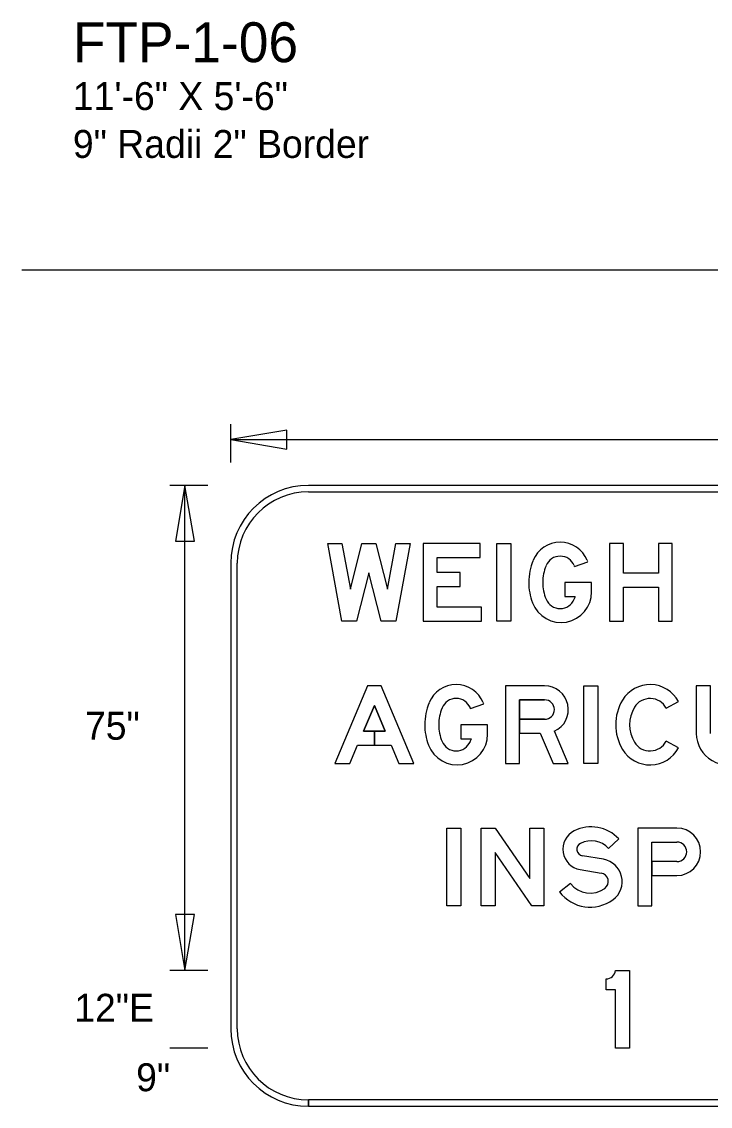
# Model space of a CAD drawing. Extents: x 0 to 770, y 0 to 495.
# Drawn here: x 0 to 86.3, y 225.2 to 361.1 of the extents above; entities that cross this region are included whole.
import ezdxf

# ---------------------------------------------------------------- set-up
doc = ezdxf.new("R2010")
doc.units = 0
for name, color, linetype in [('Dimension', 7, 'Continuous'), ('GSBWFill', 7, 'Continuous'), ('GSColorFill', 7, 'Continuous'), ('GSDims', 7, 'Continuous'), ('GSOutline', 7, 'Continuous'), ('SheetLines_dp', 7, 'Continuous'), ('TextStructures', 7, 'Continuous')]:
    doc.layers.add(name, color=color, linetype=linetype)

msp = doc.modelspace()

# ---------------------------------------------------------------- linework, layer by layer
at = {"layer": 'Dimension'}
for points in [[(26.22, 308.76), (33.24, 307.57), (33.24, 309.95)], [(20.47, 303.01), (19.28, 296), (21.66, 296)], [(20.47, 303.01), (19.28, 296), (21.66, 296)], [(20.47, 242.21), (21.66, 249.22), (19.28, 249.22)]]:
    msp.add_lwpolyline(points, close=True, dxfattribs=at)
at = {"layer": 'GSBWFill'}
for p, q in [((152.7, 303.01), (35.95, 303.01)), ((152.7, 303.01), (35.95, 303.01)), ((35.95, 302.2), (152.7, 302.2)), ((26.22, 293.28), (26.22, 234.91)), ((26.22, 293.28), (26.22, 234.91)), ((27.03, 234.91), (27.03, 293.28)), ((69.33, 292.86), (70.98, 293.45)), ((71.46, 289.65), (71.46, 290.85)), ((56.29, 275.03), (57.94, 275.62)), ((80.81, 275.09), (82.36, 275.91)), ((58.42, 271.81), (58.42, 273.01)), ((82.36, 270.12), (80.81, 270.94)), ((80.81, 270.94), (80.81, 270.94)), ((73.58, 257.51), (74.86, 258.7)), ((79, 258.29), (82.16, 258.29)), ((72.95, 256.14), (70.3, 256.59)), ((70.01, 254.86), (72.66, 254.41)), ((68.81, 253.11), (67.42, 252.04)), ((35.95, 225.18), (35.95, 225.99)), ((152.7, 225.99), (35.96, 225.99)), ((35.96, 225.99), (35.96, 225.18)), ((35.95, 225.18), (152.7, 225.18)), ((35.96, 225.18), (152.7, 225.18))]:
    msp.add_line(p, q, dxfattribs=at)
for points in [[(43.54, 292.07), (42, 285.99), (40.16, 285.99), (38.38, 295.72), (40.16, 295.72), (41.21, 289.99), (42.65, 295.72), (44.42, 295.72), (45.87, 289.99), (46.91, 295.72), (48.69, 295.72), (46.92, 285.99), (45.07, 285.99)], [(57.64, 287.74), (52.1, 287.74), (52.1, 290.35), (54.97, 290.35), (54.97, 292.11), (52.1, 292.11), (52.1, 293.96), (57.5, 293.96), (57.5, 295.72), (50.35, 295.72), (50.35, 285.99), (57.64, 285.99)], [(59.59, 285.99), (59.59, 295.72), (61.34, 295.72), (61.34, 285.99)], [(79.83, 292.02), (75.45, 292.02), (75.45, 295.72), (73.7, 295.72), (73.7, 285.99), (75.45, 285.99), (75.45, 290.27), (79.83, 290.27), (79.83, 285.99), (81.58, 285.99), (81.58, 295.72), (79.83, 295.72)], [(45.58, 272.19), (44.22, 272.19), (44.22, 270.44), (46.32, 270.44), (47.28, 268.15), (49.18, 268.15), (45.09, 277.88), (43.34, 277.88), (39.26, 268.15), (41.16, 268.15), (42.12, 270.44), (44.22, 270.44), (44.22, 272.19), (42.85, 272.19), (44.22, 275.44)], [(70.49, 268.15), (70.49, 277.88), (72.24, 277.88), (72.24, 268.15)], [(53.31, 250.31), (53.31, 260.04), (55.07, 260.04), (55.07, 250.31)], [(65.48, 260.04), (65.48, 250.31), (63.97, 250.31), (59.35, 256.98), (59.35, 250.31), (57.6, 250.31), (57.6, 260.04), (59.35, 260.04), (63.72, 253.74), (63.72, 260.04)]]:
    msp.add_lwpolyline(points, close=True, dxfattribs=at)
for points in [[(71.46, 290.85), (68.1, 290.85), (68.1, 289.1), (69.42, 289.1)], [(65.57, 277.88), (60.66, 277.88), (60.66, 268.15), (62.41, 268.15), (62.41, 276.13), (65.57, 276.13)], [(86.35, 271.92), (86.35, 277.88), (84.59, 277.88), (84.59, 271.92)], [(65.57, 273.7), (62.41, 273.7), (62.41, 271.94)], [(58.42, 273.01), (55.07, 273.01), (55.07, 271.26), (56.38, 271.26)], [(62.41, 271.94), (64.99, 271.94), (66.63, 268.15), (68.54, 268.15), (66.79, 272.2)], [(82.16, 260.04), (77.25, 260.04), (77.25, 250.31), (79, 250.31), (79, 258.29)], [(82.16, 255.86), (79, 255.86), (79, 254.11), (82.16, 254.11)], [(74.45, 242.21), (76.2, 242.21), (76.2, 232.48)], [(76.2, 232.48), (74.45, 232.48), (74.45, 239.77), (73.28, 239.77), (73.28, 241.14)]]:
    msp.add_lwpolyline(points, dxfattribs=at)
for centre, radius, start, end in [((35.95, 293.28), 9.73, 90, 180), ((35.95, 293.28), 9.73, 90, 180), ((35.95, 293.28), 8.92, 90, 180), ((67.52, 292.22), 3.67, 22.4256, 157.5744), ((67.52, 292.22), 1.92, 22.4256, 157.5744), ((70.83, 290.85), 7.25, 157.5744, 180), ((70.83, 290.85), 5.5, 157.5744, 180), ((64.21, 290.85), 5.5, 21.4721, 22.4256), ((64.21, 290.85), 7.25, 21.0425, 22.4256), ((70.83, 290.85), 7.25, 180, 200.6303), ((67.63, 289.65), 3.83, 200.6303, 0), ((70.83, 290.85), 5.5, 180, 202.4256), ((67.52, 289.49), 1.92, 202.4256, 337.5744), ((64.21, 290.85), 5.5, 337.5744, 341.4227), ((70.44, 257.4), 2.58, 116.9123, 260.4087), ((71.41, 255.49), 4.72, 42.8759, 116.9123), ((71.41, 255.49), 2.97, 42.8759, 116.9123), ((70.44, 257.4), 0.827, 116.9123, 260.4087), ((72.48, 253.36), 2.82, 306.123, 80.4087), ((72.48, 253.36), 1.07, 306.123, 80.4087), ((71.28, 255.01), 3.11, 217.5895, 306.123), ((71.28, 255.01), 4.86, 217.5895, 306.123), ((73.28, 242.31), 1.17, 270, 355.0209), ((35.95, 234.91), 9.73, 180, 270), ((35.95, 234.91), 9.73, 180, 270), ((35.95, 234.91), 8.92, 180, 270)]:
    msp.add_arc(centre, radius, start, end, dxfattribs=at)
for centre, major_axis, start_param, end_param in [((54.48, 274.38), (0, 3.67), 5.10379, 7.46258), ((65.57, 274.91), (0, 2.97), 3.562504, 6.283185), ((78.79, 274.01), (0, 4.04), 5.201543, 7.308565), ((54.48, 274.38), (0, 1.92), 5.10379, 7.46258), ((65.57, 274.91), (0, 1.22), 3.141593, 6.283185), ((80.44, 273.01), (0, 5.96), 1.025379, 2.116213), ((78.79, 274.01), (0, 2.29), 5.201543, 7.308565), ((57.79, 273.01), (0, 7.25), 1.179395, 1.570796), ((57.79, 273.01), (0, 5.5), 1.179395, 1.570796), ((51.17, 273.01), (0, 5.5), 5.087148, 5.10379), ((51.17, 273.01), (0, 7.25), 5.07965, 5.10379), ((80.44, 273.01), (0, 4.21), 1.025379, 2.116213), ((57.79, 273.01), (0, 7.25), 1.570796, 1.930863), ((57.79, 273.01), (0, 5.5), 1.570796, 1.962198), ((88.53, 271.92), (0, 3.94), 1.570796, 4.712389), ((54.59, 271.81), (0, 3.83), 1.930863, 4.712389), ((54.48, 271.65), (0, 1.92), 1.962198, 4.320988), ((51.17, 273.01), (0, 5.5), 4.320988, 4.388154), ((78.79, 272.02), (0, 2.29), 2.116213, 4.223235), ((78.79, 272.02), (0, 4.04), 2.116213, 4.223235), ((82.16, 257.08), (0, 2.97), 3.141593, 6.283185), ((82.16, 257.08), (0, 1.22), 3.141593, 6.283185)]:
    msp.add_ellipse(centre, major_axis=major_axis, ratio=0.999994, start_param=start_param, end_param=end_param, dxfattribs=at)
at = {"layer": 'GSColorFill'}
for p, q in [((69.33, 292.86), (70.98, 293.45)), ((71.46, 289.65), (71.46, 290.85)), ((56.29, 275.03), (57.94, 275.62)), ((80.81, 275.09), (82.36, 275.91)), ((58.42, 271.81), (58.42, 273.01)), ((82.36, 270.12), (80.81, 270.94)), ((80.81, 270.94), (80.81, 270.94)), ((73.58, 257.51), (74.86, 258.7)), ((79, 258.29), (82.16, 258.29)), ((72.95, 256.14), (70.3, 256.59)), ((70.01, 254.86), (72.66, 254.41)), ((68.81, 253.11), (67.42, 252.04))]:
    msp.add_line(p, q, dxfattribs=at)
for points in [[(43.54, 292.07), (42, 285.99), (40.16, 285.99), (38.38, 295.72), (40.16, 295.72), (41.21, 289.99), (42.65, 295.72), (44.42, 295.72), (45.87, 289.99), (46.91, 295.72), (48.69, 295.72), (46.92, 285.99), (45.07, 285.99)], [(57.64, 287.74), (52.1, 287.74), (52.1, 290.35), (54.97, 290.35), (54.97, 292.11), (52.1, 292.11), (52.1, 293.96), (57.5, 293.96), (57.5, 295.72), (50.35, 295.72), (50.35, 285.99), (57.64, 285.99)], [(59.59, 285.99), (59.59, 295.72), (61.34, 295.72), (61.34, 285.99)], [(79.83, 292.02), (75.45, 292.02), (75.45, 295.72), (73.7, 295.72), (73.7, 285.99), (75.45, 285.99), (75.45, 290.27), (79.83, 290.27), (79.83, 285.99), (81.58, 285.99), (81.58, 295.72), (79.83, 295.72)], [(45.58, 272.19), (44.22, 272.19), (44.22, 270.44), (46.32, 270.44), (47.28, 268.15), (49.18, 268.15), (45.09, 277.88), (43.34, 277.88), (39.26, 268.15), (41.16, 268.15), (42.12, 270.44), (44.22, 270.44), (44.22, 272.19), (42.85, 272.19), (44.22, 275.44)], [(70.49, 268.15), (70.49, 277.88), (72.24, 277.88), (72.24, 268.15)], [(53.31, 250.31), (53.31, 260.04), (55.07, 260.04), (55.07, 250.31)], [(65.48, 260.04), (65.48, 250.31), (63.97, 250.31), (59.35, 256.98), (59.35, 250.31), (57.6, 250.31), (57.6, 260.04), (59.35, 260.04), (63.72, 253.74), (63.72, 260.04)]]:
    msp.add_lwpolyline(points, close=True, dxfattribs=at)
for points in [[(71.46, 290.85), (68.1, 290.85), (68.1, 289.1), (69.42, 289.1)], [(65.57, 277.88), (60.66, 277.88), (60.66, 268.15), (62.41, 268.15), (62.41, 276.13), (65.57, 276.13)], [(86.35, 271.92), (86.35, 277.88), (84.59, 277.88), (84.59, 271.92)], [(65.57, 273.7), (62.41, 273.7), (62.41, 271.94)], [(58.42, 273.01), (55.07, 273.01), (55.07, 271.26), (56.38, 271.26)], [(62.41, 271.94), (64.99, 271.94), (66.63, 268.15), (68.54, 268.15), (66.79, 272.2)], [(82.16, 260.04), (77.25, 260.04), (77.25, 250.31), (79, 250.31), (79, 258.29)], [(82.16, 255.86), (79, 255.86), (79, 254.11), (82.16, 254.11)], [(74.45, 242.21), (76.2, 242.21), (76.2, 232.48)], [(76.2, 232.48), (74.45, 232.48), (74.45, 239.77), (73.28, 239.77), (73.28, 241.14)]]:
    msp.add_lwpolyline(points, dxfattribs=at)
for centre, radius, start, end in [((67.52, 292.22), 3.67, 22.4256, 157.5744), ((67.52, 292.22), 1.92, 22.4256, 157.5744), ((70.83, 290.85), 7.25, 157.5744, 180), ((70.83, 290.85), 5.5, 157.5744, 180), ((64.21, 290.85), 5.5, 21.4721, 22.4256), ((64.21, 290.85), 7.25, 21.0425, 22.4256), ((70.83, 290.85), 7.25, 180, 200.6303), ((67.63, 289.65), 3.83, 200.6303, 0), ((70.83, 290.85), 5.5, 180, 202.4256), ((67.52, 289.49), 1.92, 202.4256, 337.5744), ((64.21, 290.85), 5.5, 337.5744, 341.4227), ((70.44, 257.4), 2.58, 116.9123, 260.4087), ((71.41, 255.49), 4.72, 42.8759, 116.9123), ((71.41, 255.49), 2.97, 42.8759, 116.9123), ((70.44, 257.4), 0.827, 116.9123, 260.4087), ((72.48, 253.36), 2.82, 306.123, 80.4087), ((72.48, 253.36), 1.07, 306.123, 80.4087), ((71.28, 255.01), 3.11, 217.5895, 306.123), ((71.28, 255.01), 4.86, 217.5895, 306.123), ((73.28, 242.31), 1.17, 270, 355.0209)]:
    msp.add_arc(centre, radius, start, end, dxfattribs=at)
for centre, major_axis, start_param, end_param in [((54.48, 274.38), (0, 3.67), 5.10379, 7.46258), ((65.57, 274.91), (0, 2.97), 3.562504, 6.283185), ((78.79, 274.01), (0, 4.04), 5.201543, 7.308565), ((54.48, 274.38), (0, 1.92), 5.10379, 7.46258), ((65.57, 274.91), (0, 1.22), 3.141593, 6.283185), ((80.44, 273.01), (0, 5.96), 1.025379, 2.116213), ((78.79, 274.01), (0, 2.29), 5.201543, 7.308565), ((57.79, 273.01), (0, 7.25), 1.179395, 1.570796), ((57.79, 273.01), (0, 5.5), 1.179395, 1.570796), ((51.17, 273.01), (0, 5.5), 5.087148, 5.10379), ((51.17, 273.01), (0, 7.25), 5.07965, 5.10379), ((80.44, 273.01), (0, 4.21), 1.025379, 2.116213), ((57.79, 273.01), (0, 7.25), 1.570796, 1.930863), ((57.79, 273.01), (0, 5.5), 1.570796, 1.962198), ((88.53, 271.92), (0, 3.94), 1.570796, 4.712389), ((54.59, 271.81), (0, 3.83), 1.930863, 4.712389), ((54.48, 271.65), (0, 1.92), 1.962198, 4.320988), ((51.17, 273.01), (0, 5.5), 4.320988, 4.388154), ((78.79, 272.02), (0, 2.29), 2.116213, 4.223235), ((78.79, 272.02), (0, 4.04), 2.116213, 4.223235), ((82.16, 257.08), (0, 2.97), 3.141593, 6.283185), ((82.16, 257.08), (0, 1.22), 3.141593, 6.283185)]:
    msp.add_ellipse(centre, major_axis=major_axis, ratio=0.999994, start_param=start_param, end_param=end_param, dxfattribs=at)
at = {"layer": 'GSDims'}
for p, q in [((26.22, 305.89), (26.22, 310.67)), ((26.22, 308.76), (162.43, 308.76)), ((23.35, 303.01), (18.56, 303.01)), ((20.47, 242.21), (20.47, 303.01)), ((23.35, 242.21), (18.56, 242.21)), ((23.35, 242.21), (18.56, 242.21)), ((23.35, 232.48), (18.56, 232.48)), ((23.35, 232.48), (18.56, 232.48))]:
    msp.add_line(p, q, dxfattribs=at)
at = {"layer": 'GSOutline'}
for p, q in [((69.33, 292.86), (70.98, 293.45)), ((71.46, 289.65), (71.46, 290.85)), ((56.29, 275.03), (57.94, 275.62)), ((80.81, 275.09), (82.36, 275.91)), ((62.41, 273.7), (65.57, 273.7)), ((58.42, 271.81), (58.42, 273.01)), ((82.36, 270.12), (80.81, 270.94)), ((80.81, 270.94), (80.81, 270.94)), ((73.58, 257.51), (74.86, 258.7)), ((79, 258.29), (82.16, 258.29)), ((72.95, 256.14), (70.3, 256.59)), ((70.01, 254.86), (72.66, 254.41)), ((68.81, 253.11), (67.42, 252.04)), ((79, 254.11), (82.16, 254.11))]:
    msp.add_line(p, q, dxfattribs=at)
for points in [[(43.54, 292.07), (42, 285.99), (40.16, 285.99), (38.38, 295.72), (40.16, 295.72), (41.21, 289.99), (42.65, 295.72), (44.42, 295.72), (45.87, 289.99), (46.91, 295.72), (48.69, 295.72), (46.92, 285.99), (45.07, 285.99)], [(57.64, 287.74), (52.1, 287.74), (52.1, 290.35), (54.97, 290.35), (54.97, 292.11), (52.1, 292.11), (52.1, 293.96), (57.5, 293.96), (57.5, 295.72), (50.35, 295.72), (50.35, 285.99), (57.64, 285.99)], [(59.59, 285.99), (59.59, 295.72), (61.34, 295.72), (61.34, 285.99)], [(79.83, 292.02), (75.45, 292.02), (75.45, 295.72), (73.7, 295.72), (73.7, 285.99), (75.45, 285.99), (75.45, 290.27), (79.83, 290.27), (79.83, 285.99), (81.58, 285.99), (81.58, 295.72), (79.83, 295.72)], [(42.12, 270.44), (46.32, 270.44), (47.28, 268.15), (49.18, 268.15), (45.09, 277.88), (43.34, 277.88), (39.26, 268.15), (41.16, 268.15)], [(70.49, 268.15), (70.49, 277.88), (72.24, 277.88), (72.24, 268.15)], [(45.58, 272.19), (44.22, 275.44), (42.85, 272.19)], [(53.31, 250.31), (53.31, 260.04), (55.07, 260.04), (55.07, 250.31)], [(65.48, 260.04), (65.48, 250.31), (63.97, 250.31), (59.35, 256.98), (59.35, 250.31), (57.6, 250.31), (57.6, 260.04), (59.35, 260.04), (63.72, 253.74), (63.72, 260.04)]]:
    msp.add_lwpolyline(points, close=True, dxfattribs=at)
for points in [[(71.46, 290.85), (68.1, 290.85), (68.1, 289.1), (69.42, 289.1)], [(65.57, 277.88), (60.66, 277.88), (60.66, 268.15), (62.41, 268.15), (62.41, 271.94), (64.99, 271.94)], [(86.35, 271.92), (86.35, 277.88), (84.59, 277.88), (84.59, 271.92)], [(65.57, 276.13), (62.41, 276.13), (62.41, 273.7)], [(58.42, 273.01), (55.07, 273.01), (55.07, 271.26), (56.38, 271.26)], [(64.99, 271.94), (66.63, 268.15), (68.54, 268.15), (66.79, 272.2)], [(82.16, 260.04), (77.25, 260.04), (77.25, 250.31), (79, 250.31), (79, 254.11)], [(82.16, 255.86), (79, 255.86), (79, 258.29)], [(74.45, 242.21), (76.2, 242.21), (76.2, 232.48)], [(76.2, 232.48), (74.45, 232.48), (74.45, 239.77), (73.28, 239.77), (73.28, 241.14)]]:
    msp.add_lwpolyline(points, dxfattribs=at)
for centre, radius, start, end in [((67.52, 292.22), 3.67, 22.4256, 157.5744), ((67.52, 292.22), 1.92, 22.4256, 157.5744), ((70.83, 290.85), 7.25, 157.5744, 180), ((70.83, 290.85), 5.5, 157.5744, 180), ((64.21, 290.85), 5.5, 21.4721, 22.4256), ((64.21, 290.85), 7.25, 21.0425, 22.4256), ((70.83, 290.85), 7.25, 180, 200.6303), ((67.63, 289.65), 3.83, 200.6303, 0), ((70.83, 290.85), 5.5, 180, 202.4256), ((67.52, 289.49), 1.92, 202.4256, 337.5744), ((64.21, 290.85), 5.5, 337.5744, 341.4227), ((70.44, 257.4), 2.58, 116.9123, 260.4087), ((71.41, 255.49), 4.72, 42.8759, 116.9123), ((71.41, 255.49), 2.97, 42.8759, 116.9123), ((70.44, 257.4), 0.827, 116.9123, 260.4087), ((72.48, 253.36), 2.82, 306.123, 80.4087), ((72.48, 253.36), 1.07, 306.123, 80.4087), ((71.28, 255.01), 3.11, 217.5895, 306.123), ((71.28, 255.01), 4.86, 217.5895, 306.123), ((73.28, 242.31), 1.17, 270, 355.0209)]:
    msp.add_arc(centre, radius, start, end, dxfattribs=at)
for centre, major_axis, start_param, end_param in [((54.48, 274.38), (0, 3.67), 5.10379, 7.46258), ((65.57, 274.91), (0, 2.97), 3.562504, 6.283185), ((78.79, 274.01), (0, 4.04), 5.201543, 7.308565), ((54.48, 274.38), (0, 1.92), 5.10379, 7.46258), ((65.57, 274.91), (0, 1.22), 3.141593, 6.283185), ((80.44, 273.01), (0, 5.96), 1.025379, 2.116213), ((78.79, 274.01), (0, 2.29), 5.201543, 7.308565), ((57.79, 273.01), (0, 7.25), 1.179395, 1.570796), ((57.79, 273.01), (0, 5.5), 1.179395, 1.570796), ((51.17, 273.01), (0, 5.5), 5.087148, 5.10379), ((51.17, 273.01), (0, 7.25), 5.07965, 5.10379), ((80.44, 273.01), (0, 4.21), 1.025379, 2.116213), ((57.79, 273.01), (0, 7.25), 1.570796, 1.930863), ((57.79, 273.01), (0, 5.5), 1.570796, 1.962198), ((88.53, 271.92), (0, 3.94), 1.570796, 4.712389), ((54.59, 271.81), (0, 3.83), 1.930863, 4.712389), ((54.48, 271.65), (0, 1.92), 1.962198, 4.320988), ((51.17, 273.01), (0, 5.5), 4.320988, 4.388154), ((78.79, 272.02), (0, 2.29), 2.116213, 4.223235), ((78.79, 272.02), (0, 4.04), 2.116213, 4.223235), ((82.16, 257.08), (0, 2.97), 3.141593, 6.283185), ((82.16, 257.08), (0, 1.22), 3.141593, 6.283185)]:
    msp.add_ellipse(centre, major_axis=major_axis, ratio=0.999994, start_param=start_param, end_param=end_param, dxfattribs=at)
at = {"layer": 'SheetLines_dp'}
msp.add_line((770, 330), (0, 330), dxfattribs=at)

# ---------------------------------------------------------------- texts
at = {"layer": 'TextStructures'}
for s, height, p in [('FTP-1-06', 5, (6.42, 356.06)), ('11\'-6" X 5\'-6"', 3.5, (6.42, 350.06)), ('9" Radii 2" Border', 3.5, (6.42, 344.06)), ('75"', 3.5, (7.94, 271.13)), ('12"E', 3.5, (6.59, 235.78)), ('9"', 3.5, (14.35, 227.07))]:
    msp.add_text(s, height=height, dxfattribs=at).set_placement(p)

doc.saveas('drawing.dxf')
